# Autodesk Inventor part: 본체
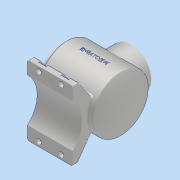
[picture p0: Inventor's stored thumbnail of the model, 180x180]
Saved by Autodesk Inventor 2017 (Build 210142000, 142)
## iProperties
Part Number: 본체
Material: 알루미늄 6061
Document SubType Name: Modeling
Designer: MRC
Density: 2.7 g/cm^3
Appearance: 알루미늄 - 평지
Mass: 1292.13 g
Surface Area: 1061.65 cm^2
Volume: 478.566 cm^3
Author: MRC
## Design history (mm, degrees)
sketch "스케치7"
  geometry: L1 (0, 0)-(120, 0); L2 (0, 0)-(0, 36); L3 (0, 36)-(12, 36); L4 (12, 36)-(12, 50); L5 (12, 50)-(108.336, 50); A1 r 113 centre (7, 0) between (120, 0) and (108.336, 50)
  constraints: 10 end point, 2 horizontal, 2 perpendicular, 2 point on circle, 1 centre point, 1 point on line, 1 vertical
  dimensions: "d11" = 120 distance of L1.start L1.end; "d12" = 72 diameter of L3 L1; "d13" = 100 diameter of L5 L1; "d14" = 113 radius of A1; "d15" = 12 distance of L2.end L3.end
revolve "회전1" sketch "스케치7" stored, may be unused: angle "d16" = 90 deg
sketch "스케치8"
  geometry: L1 (0, 0)-(0, 27); L2 (0, -36)-(0, 36) reference; L3 (0, 27)-(19, 27); L4 (19, 27)-(19, 43); L5 (19, 43)-(104.499, 43); L6 (0, 0)-(120, 0); A1 r 113 centre (0, 0) between (113, 0) and (104.499, 43); A2 r 113 centre (7, 0) between (108.336, -50) and (108.336, 50) reference
  constraints: 10 end point, 3 point on circle, 3 point on line, 2 horizontal, 2 perpendicular, 1 centre point
  dimensions: "d17" = 54 diameter of L3 L6; "d18" = 86 diameter of L5 L6; "d19" = 19 distance of L1.end L3.end; "d20" = 113 radius of A1; "d102" = 7 distance of A2.centre A1.centre
revolve "회전2" sketch "스케치8" stored, may be unused: angle "d22" = 90 deg
node "작업 평면1"
sketch "스케치9"
  geometry: C1 r 36 at (-62, 0); 1 further point
  constraints: 1 centre point, 1 horizontal alignment
  dimensions: "d24" = 72 diameter of C1; "d25" = 62 distance of point (0, 0) C1.centre
extrude "돌출2" join sketch "스케치9" stored distance "d26" = 12; taper "d27" = 0 deg
sketch "스케치10"
  geometry: C1 r 36 at (0, 0) reference; C2 r 27 at (0, 0); 1 further point
  constraints: 1 centre point, 1 coincident
  dimensions: "d28" = 54 diameter of C2
extrude "돌출3" cut sketch "스케치10" distance "d29" = 47.75; taper "d30" = 0 deg
sketch "스케치11"
  geometry: C1 r 27 at (0, 0) reference; 2 further points
  constraints: 1 vertical alignment
  dimensions: "d31" = 32.5 distance of point (0, 32.5) C1.centre
hole "구멍1" sketch "스케치11" at (0, 32.5) diameter "d32" = 3.242; stored, may be unused: countersink angle "d36" = 90 deg, drill point angle "d38" = 118 deg; dims "d33" = 8, "d34" = 4, "d35" = 2, "d37" = 10
node "작업 평면2"
sketch "스케치12"
  geometry: L1 (-42.278, -26.694)-(-67, -62); L2 (-67, -62)-(-77, -62); L3 (-77, -62)-(-77, 62); L4 (-77, 62)-(-67, 62); L5 (-67, 62)-(-42.278, 26.694); A1 r 50 centre (0, 0) between (-42.278, -26.694) and (-42.278, 26.694) reference; 1 further point
  constraints: 10 end point, 2 perpendicular, 2 point on circle, 1 horizontal
  dimensions: "d43" = 10 distance of L3.end L4.end; "d44" = 77 distance from line of L3 point (0, 0); "d45" = 10 distance of L1.end L2.end; "d46" = 55 deg angle of L4 L5; "d47" = 55 deg angle of L2 L1; "d48" = 124 distance of L2.end L3.end; "d49" = 62 vertical distance of L2.end point (0, 0)
extrude "돌출4" join sketch "스케치12" stored distance "d50" = 80; taper "d51" = 0 deg
sketch "스케치13"
  geometry: L1 (62, -77)-(-62, -77) reference; A1 r 52.096 centre (0, -112.096) between (38.5, -77) and (-38.5, -77); 1 further point
  constraints: 2 point on circle, 2 point on line, 1 centre point, 1 vertical alignment
  dimensions: "d52" = 17 distance edge to line of A1 L1; "d53" = 77 distance of A1.start A1.end
extrude "돌출5" cut sketch "스케치13" distance "d54" = 80; taper "d55" = 0 deg
sketch "스케치14"
  geometry: 2 further points
  constraints: 1 vertical alignment
  dimensions: "d56" = 32.5 distance of point (0, 32.5) point (0, 0)
hole "구멍2" sketch "스케치14" at (0, 32.5) diameter "d57" = 3.242; stored, may be unused: countersink angle "d61" = 90 deg, drill point angle "d63" = 118 deg; dims "d58" = 8, "d59" = 4, "d60" = 2, "d62" = 10
sketch "스케치15"
  geometry: L1 (80, 23.5)-(80, 0) reference; L2 (0, 0)-(80, 0) reference; C1 r 4.5 at (60, 8); 1 further point
  constraints: 1 centre point
  dimensions: "d67" = 9 diameter of C1; "d68" = 20 distance from line of C1.centre L1; "d69" = 8 distance from line of C1.centre L2
extrude "돌출6" cut sketch "스케치15" distance "d70" = 6; taper "d71" = 0 deg
sketch "스케치16"
  geometry: L1 (7, -8)-(7, 0); L2 (-7, 0)-(-7, -8); L3 (-7, -8)-(7, -8); L4 (-60, -8)-(20, -8) reference; C1 r 4.5 at (0, 0) reference; A1 r 7 centre (0, 0) between (7, 0) and (-7, 0); 1 further point
  constraints: 6 end point, 2 point on circle, 2 tangent, 1 centre point, 1 coincident, 1 perpendicular, 1 point on line, 1 vertical
  dimensions: "d89" = 14 distance of L2.end L1.start; "d90" = 7 radius of A1
extrude "돌출7" cut sketch "스케치16" distance "d73" = 27.5; taper "d74" = 0 deg
chamfer "모따기1" distance "d81" = 1; stored, may be unused: second distance "d82" = 2, angle "d83" = 45 deg
chamfer "모따기2" distance "d84" = 1; stored, may be unused: second distance "d85" = 2, angle "d86" = 45 deg
fillet "모깎기1" dims "d87" = 3
fillet "모깎기2" dims "d88" = 3
fillet "모깎기3" dims "d94" = 3
fillet "모깎기4" dims "d95" = 3
fillet "모깎기5" dims "d96" = 3
node "작업 평면3"
sketch "스케치17"
  geometry: L1 (0, -36)-(0, 36) reference; 3 further points
  constraints: 1 horizontal alignment, 1 midpoint, 1 other
  dimensions: "d98" = 62 distance from line of point (62, 0) L1
feature "엠보싱1" sketch "스케치17" dims "d11" = 120, "d12" = 72, "d13" = 100, "d14" = 113, "d15" = 12, "d99" = 0.5, "d100" = 0
fillet "모깎기6" dims "d103" = 3
node "솔리드2"
pattern_circular "원형 패턴1" dims angle "d40" = 360 deg
pattern_circular "원형 패턴2" dims angle "d65" = 360 deg
pattern_linear "직사각형 패턴2" dims "d93" = 40
mirror "미러1"
node "투영된 루프1"
node "투영된 루프2"
other parameters: "d23" = 65, "d97" = 101
